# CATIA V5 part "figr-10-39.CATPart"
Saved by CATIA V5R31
Part number: Part1
Bounding box of the stored display mesh (mm): x 0 to 56, y -58.044 to 12.863, z -44.68 to 88.822
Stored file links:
  D:\PROJECTS\Project 2021\US EDITION\CATIA V5 6R 2021\Resources\Part Files\c10_catia_v5_6r2021_prt\c10_catia_v5_6r2021_prt\figr-10-39.CATPart
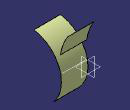
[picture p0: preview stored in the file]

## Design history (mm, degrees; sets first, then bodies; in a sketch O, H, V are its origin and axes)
Body1 (main body)
  Sketch1 on yz-plane, origin (0, 0, 0), H (0, 1, 0), V (0, 0, 1)
    arc A1 centre (-66.8734, 0) radius 66.8734 from (-58.0438, 66.2879) to (-17.1165, -44.68) cw
    coincidence: A1 O
    tangency: A1 V
  Extrude1: Element1 Sketch1, Lim1 56, Lim2 0
  Sketch2 on zx-plane, origin (0, 0, 0), H (-1, 0, 0), V (0, 0, 1)
    line L1 (-55.482, 13.9185) -> (0, 13.9185)
    point P1 (0, 13.9185)
    coincidence: P1 V
    horizontal: L1 H
  Project1: ToProject Sketch2, Support Extrude1
  Sweep1: type Circle, Guide Project1, Reference Extrude1, Radius 100, Angle1 20, Angle2 45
